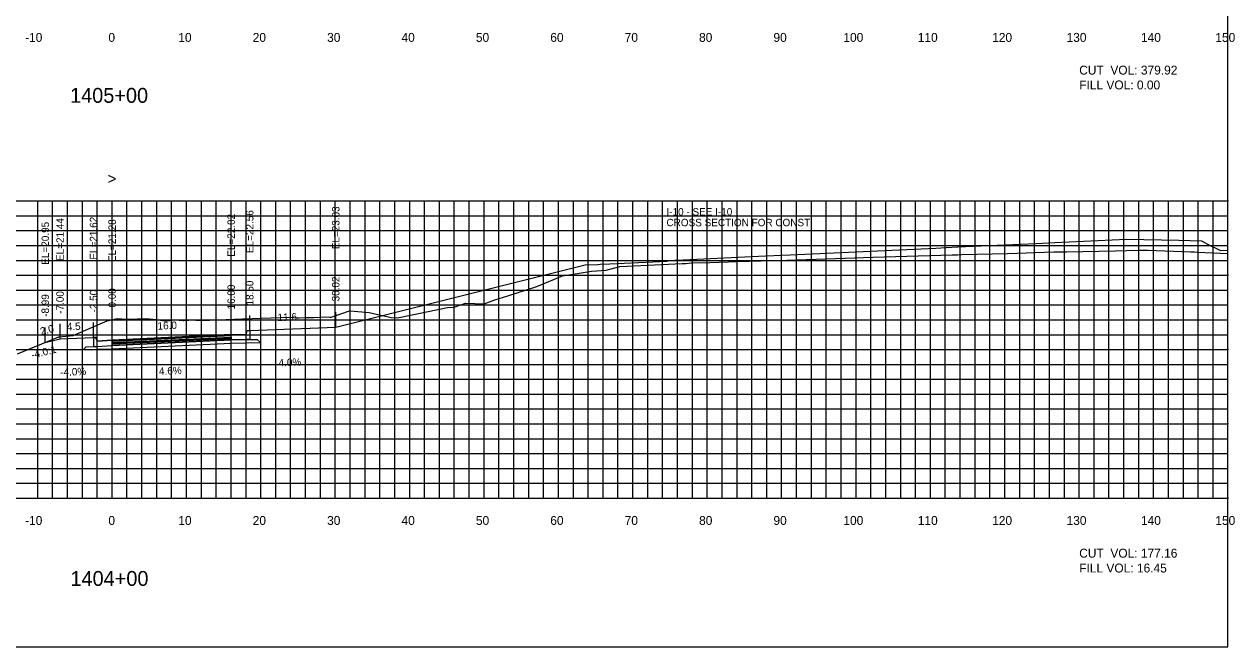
# Model space of a CAD drawing. Extents: x 1797652 to 1804159, y 242516 to 246906.
# Drawn here: x 1803312.7 to 1803475.4, y 242516 to 242599.8 of the extents above; entities that cross this region are included whole.
import ezdxf

# ---------------------------------------------------------------- set-up
doc = ezdxf.new("R2010")
doc.units = 0
for name, color, linetype in [('1', 7, 'Continuous'), ('10', 7, 'Continuous'), ('2', 7, 'Continuous'), ('3', 7, 'Continuous'), ('4', 7, 'Continuous'), ('60', 7, 'Continuous'), ('BASE', 7, 'Continuous'), ('CL-CNST', 7, 'Continuous'), ('Level 62', 7, 'Continuous'), ('LOWER BINDER', 7, 'Continuous'), ('M-ROADS', 7, 'Continuous'), ('UPPER BINDER', 7, 'Continuous')]:
    doc.layers.add(name, color=color, linetype=linetype)

msp = doc.modelspace()

# ---------------------------------------------------------------- linework, layer by layer
for p, q in [((1803342.99, 242558.56), (1803342.99, 242560.56)), ((1803354.55, 242559.03), (1803354.55, 242561.03)), ((1803315.5, 242556.95), (1803315.5, 242558.95)), ((1803317.49, 242557.44), (1803317.49, 242559.44)), ((1803321.99, 242557.62), (1803321.99, 242559.62)), ((1803324.49, 242557.28), (1803324.49, 242559.28)), ((1803340.49, 242558.02), (1803340.49, 242560.02))]:
    msp.add_line(p, q)
for points in [[(1803174.49, 242516), (1803474.49, 242516), (1803474.49, 242706), (1803174.49, 242706)], [(1803340.49, 242558.02), (1803342.49, 242558.06), (1803342.66, 242558.56), (1803342.99, 242558.56), (1803342.99, 242557.34), (1803342.49, 242557.34), (1803340.49, 242557.3)], [(1803324.49, 242557.28), (1803322.49, 242557.12), (1803322.32, 242557.62), (1803321.99, 242557.62), (1803321.98, 242556.4), (1803322.48, 242556.4), (1803324.49, 242556.56)]]:
    msp.add_lwpolyline(points, close=True)
at = {"layer": '2'}
msp.add_lwpolyline([(1803340.49, 242557.87), (1803340.49, 242558.02), (1803324.49, 242557.28), (1803324.49, 242557.13)], close=True, dxfattribs=at)
at = {"layer": '60'}
for p, q in [((1803474.49, 242536), (1803474.49, 242576)), ((1803474.55, 242576), (1803474.49, 242576)), ((1803474.55, 242566), (1803474.49, 242566)), ((1803474.55, 242556), (1803474.49, 242556)), ((1803474.55, 242546), (1803474.49, 242546)), ((1803174.49, 242536), (1803474.49, 242536)), ((1803314.49, 242535.94), (1803314.49, 242536)), ((1803324.49, 242535.94), (1803324.49, 242536)), ((1803334.49, 242535.94), (1803334.49, 242536)), ((1803344.49, 242535.94), (1803344.49, 242536)), ((1803354.49, 242535.94), (1803354.49, 242536)), ((1803364.49, 242535.94), (1803364.49, 242536)), ((1803374.49, 242535.94), (1803374.49, 242536)), ((1803384.49, 242535.94), (1803384.49, 242536)), ((1803394.49, 242535.94), (1803394.49, 242536)), ((1803404.49, 242535.94), (1803404.49, 242536)), ((1803414.49, 242535.94), (1803414.49, 242536)), ((1803424.49, 242535.94), (1803424.49, 242536)), ((1803434.49, 242535.94), (1803434.49, 242536)), ((1803444.49, 242535.94), (1803444.49, 242536)), ((1803454.49, 242535.94), (1803454.49, 242536)), ((1803464.49, 242535.94), (1803464.49, 242536)), ((1803474.49, 242535.94), (1803474.49, 242536)), ((1803474.55, 242536), (1803474.49, 242536))]:
    msp.add_line(p, q, dxfattribs=at)
at = {"layer": 'BASE'}
msp.add_lwpolyline([(1803324.49, 242556.56), (1803340.49, 242557.3), (1803342.49, 242557.34), (1803342.99, 242557.34), (1803343.99, 242557.37), (1803344.47, 242556.89), (1803340.49, 242556.8), (1803324.49, 242556.06), (1803320.58, 242555.98), (1803320.98, 242556.38), (1803321.98, 242556.4), (1803322.48, 242556.4)], close=True, dxfattribs=at)
at = {"layer": 'CL-CNST'}
for points in [[(1803354.55, 242559.03), (1803383.24, 242566.17), (1803388.08, 242567.38), (1803389.79, 242567.46), (1803390.1, 242567.47), (1803391.39, 242567.53), (1803399.12, 242567.9), (1803399.19, 242567.97), (1803399.2, 242567.98), (1803400.12, 242568.01), (1803400.21, 242568.02), (1803401.24, 242568.07), (1803412.34, 242568.59), (1803415.62, 242568.74), (1803424.47, 242569.15), (1803435.2, 242569.66), (1803436.59, 242569.72), (1803438.18, 242569.8), (1803448.71, 242570.29), (1803451.21, 242570.41), (1803460.83, 242570.86), (1803467.87, 242570.7), (1803470.93, 242570.63), (1803471.75, 242570.2), (1803473.46, 242569.32), (1803474.49, 242569.37)], [(1803315.5, 242556.95), (1803317.49, 242557.44), (1803321.99, 242557.62), (1803322.32, 242557.62), (1803322.49, 242557.12), (1803324.49, 242557.28), (1803340.49, 242558.02), (1803342.49, 242558.06), (1803342.66, 242558.56), (1803342.99, 242558.56), (1803354.55, 242559.03)]]:
    msp.add_lwpolyline(points, dxfattribs=at)
at = {"layer": 'Level 62'}
for p, q in [((1803174.49, 242576), (1803474.49, 242576)), ((1803314.49, 242536), (1803314.49, 242576)), ((1803316.49, 242536), (1803316.49, 242576)), ((1803318.49, 242536), (1803318.49, 242576)), ((1803320.49, 242536), (1803320.49, 242576)), ((1803322.49, 242536), (1803322.49, 242576)), ((1803324.49, 242536), (1803324.49, 242576)), ((1803326.49, 242536), (1803326.49, 242576)), ((1803328.49, 242536), (1803328.49, 242576)), ((1803330.49, 242536), (1803330.49, 242576)), ((1803332.49, 242536), (1803332.49, 242576)), ((1803334.49, 242536), (1803334.49, 242576)), ((1803336.49, 242536), (1803336.49, 242576)), ((1803338.49, 242536), (1803338.49, 242576)), ((1803340.49, 242536), (1803340.49, 242576)), ((1803342.49, 242536), (1803342.49, 242576)), ((1803344.49, 242536), (1803344.49, 242576)), ((1803346.49, 242536), (1803346.49, 242576)), ((1803348.49, 242536), (1803348.49, 242576)), ((1803350.49, 242536), (1803350.49, 242576)), ((1803352.49, 242536), (1803352.49, 242576)), ((1803354.49, 242536), (1803354.49, 242576)), ((1803356.49, 242536), (1803356.49, 242576)), ((1803358.49, 242536), (1803358.49, 242576)), ((1803360.49, 242536), (1803360.49, 242576)), ((1803362.49, 242536), (1803362.49, 242576)), ((1803364.49, 242536), (1803364.49, 242576)), ((1803366.49, 242536), (1803366.49, 242576)), ((1803368.49, 242536), (1803368.49, 242576)), ((1803370.49, 242536), (1803370.49, 242576)), ((1803372.49, 242536), (1803372.49, 242576)), ((1803374.49, 242536), (1803374.49, 242576)), ((1803376.49, 242536), (1803376.49, 242576)), ((1803378.49, 242536), (1803378.49, 242576)), ((1803380.49, 242536), (1803380.49, 242576)), ((1803382.49, 242536), (1803382.49, 242576)), ((1803384.49, 242536), (1803384.49, 242576)), ((1803386.49, 242536), (1803386.49, 242576)), ((1803388.49, 242536), (1803388.49, 242576)), ((1803390.49, 242536), (1803390.49, 242576)), ((1803392.49, 242536), (1803392.49, 242576)), ((1803394.49, 242536), (1803394.49, 242576)), ((1803396.49, 242536), (1803396.49, 242576)), ((1803398.49, 242536), (1803398.49, 242576)), ((1803400.49, 242536), (1803400.49, 242576)), ((1803402.49, 242536), (1803402.49, 242576)), ((1803404.49, 242536), (1803404.49, 242576)), ((1803406.49, 242536), (1803406.49, 242576)), ((1803408.49, 242536), (1803408.49, 242576)), ((1803410.49, 242536), (1803410.49, 242576)), ((1803412.49, 242536), (1803412.49, 242576)), ((1803414.49, 242536), (1803414.49, 242576)), ((1803416.49, 242536), (1803416.49, 242576)), ((1803418.49, 242536), (1803418.49, 242576)), ((1803420.49, 242536), (1803420.49, 242576)), ((1803422.49, 242536), (1803422.49, 242576)), ((1803424.49, 242536), (1803424.49, 242576)), ((1803426.49, 242536), (1803426.49, 242576)), ((1803428.49, 242536), (1803428.49, 242576)), ((1803430.49, 242536), (1803430.49, 242576)), ((1803432.49, 242536), (1803432.49, 242576)), ((1803434.49, 242536), (1803434.49, 242576)), ((1803436.49, 242536), (1803436.49, 242576)), ((1803438.49, 242536), (1803438.49, 242576)), ((1803440.49, 242536), (1803440.49, 242576)), ((1803442.49, 242536), (1803442.49, 242576)), ((1803444.49, 242536), (1803444.49, 242576)), ((1803446.49, 242536), (1803446.49, 242576)), ((1803448.49, 242536), (1803448.49, 242576)), ((1803450.49, 242536), (1803450.49, 242576)), ((1803452.49, 242536), (1803452.49, 242576)), ((1803454.49, 242536), (1803454.49, 242576)), ((1803456.49, 242536), (1803456.49, 242576)), ((1803458.49, 242536), (1803458.49, 242576)), ((1803460.49, 242536), (1803460.49, 242576)), ((1803462.49, 242536), (1803462.49, 242576)), ((1803464.49, 242536), (1803464.49, 242576)), ((1803466.49, 242536), (1803466.49, 242576)), ((1803468.49, 242536), (1803468.49, 242576)), ((1803470.49, 242536), (1803470.49, 242576)), ((1803472.49, 242536), (1803472.49, 242576)), ((1803474.49, 242536), (1803474.49, 242576)), ((1803174.49, 242574), (1803474.49, 242574)), ((1803174.49, 242572), (1803474.49, 242572)), ((1803174.49, 242570), (1803474.49, 242570)), ((1803174.49, 242568), (1803474.49, 242568)), ((1803174.49, 242566), (1803474.49, 242566)), ((1803174.49, 242564), (1803474.49, 242564)), ((1803174.49, 242562), (1803474.49, 242562)), ((1803174.49, 242560), (1803474.49, 242560)), ((1803174.49, 242558), (1803474.49, 242558)), ((1803174.49, 242556), (1803474.49, 242556)), ((1803174.49, 242554), (1803474.49, 242554)), ((1803174.49, 242552), (1803474.49, 242552)), ((1803174.49, 242550), (1803474.49, 242550)), ((1803174.49, 242548), (1803474.49, 242548)), ((1803174.49, 242546), (1803474.49, 242546)), ((1803174.49, 242544), (1803474.49, 242544)), ((1803174.49, 242542), (1803474.49, 242542)), ((1803174.49, 242540), (1803474.49, 242540)), ((1803174.49, 242538), (1803474.49, 242538)), ((1803174.49, 242536), (1803474.49, 242536))]:
    msp.add_line(p, q, dxfattribs=at)
at = {"layer": 'LOWER BINDER'}
for points in [[(1803324.49, 242556.75), (1803324.49, 242556.94), (1803340.49, 242557.68), (1803340.49, 242557.49)], [(1803324.49, 242556.56), (1803324.49, 242556.75), (1803340.49, 242557.49), (1803340.49, 242557.3)]]:
    msp.add_lwpolyline(points, close=True, dxfattribs=at)
at = {"layer": 'M-ROADS'}
msp.add_lwpolyline([(1803311.78, 242555.42), (1803317.34, 242557.7), (1803319.26, 242557.91), (1803323.83, 242559.87), (1803325.17, 242560.18), (1803326.45, 242560.1), (1803326.69, 242560.1), (1803329.06, 242560.18), (1803330.39, 242560.06), (1803330.7, 242560.02), (1803331.2, 242559.9), (1803331.51, 242559.86), (1803331.9, 242559.88), (1803332.94, 242559.99), (1803332.97, 242559.99), (1803334.04, 242559.92), (1803334.15, 242559.92), (1803334.2, 242559.94), (1803334.29, 242559.93), (1803335.26, 242560), (1803335.76, 242559.97), (1803336.47, 242559.89), (1803342.02, 242560.11), (1803348.44, 242560.36), (1803349.32, 242560.26), (1803349.63, 242560.26), (1803350.54, 242560.31), (1803350.72, 242560.31), (1803351.21, 242560.31), (1803351.6, 242560.31), (1803351.94, 242560.34), (1803352.08, 242560.33), (1803353, 242560.38), (1803353.74, 242560.37), (1803353.95, 242560.37), (1803356.38, 242561.19), (1803356.47, 242561.19), (1803356.55, 242561.23), (1803359.06, 242560.99), (1803361.98, 242560.33), (1803362.83, 242560.26), (1803369.57, 242561.67), (1803370.45, 242561.72), (1803371.98, 242562.22), (1803374.52, 242562.16), (1803375.95, 242562.68), (1803377.68, 242563.24), (1803381.59, 242564.5), (1803385.04, 242565.94), (1803387.52, 242566.32), (1803388.95, 242566.55), (1803390.92, 242566.69), (1803392.74, 242567.18), (1803392.78, 242567.18), (1803401.1, 242567.56), (1803401.61, 242567.59), (1803402.36, 242567.66), (1803404.83, 242567.72), (1803408.54, 242567.84), (1803411.75, 242567.92), (1803413.89, 242567.98), (1803423.02, 242568.28), (1803426.76, 242568.41), (1803437.43, 242568.74), (1803438.11, 242568.76), (1803438.65, 242568.77), (1803444.83, 242568.94), (1803451.1, 242569.14), (1803451.64, 242569.15), (1803452.8, 242569.17), (1803459.37, 242569.29), (1803462.41, 242569.35), (1803463.12, 242569.35), (1803463.68, 242569.35), (1803469.5, 242569.15), (1803469.99, 242569.14), (1803470.36, 242569.12), (1803474.49, 242568.94)], dxfattribs=at)
at = {"layer": 'UPPER BINDER'}
msp.add_lwpolyline([(1803340.49, 242557.68), (1803340.49, 242557.87), (1803324.49, 242557.13), (1803324.49, 242556.94)], close=True, dxfattribs=at)

# ---------------------------------------------------------------- texts
msp.add_text('-4.0:1', height=1, rotation=14.0362).set_placement((1803313.75, 242554.77))
at = {"layer": '1'}
for s, p in [('1405+00', (1803318.84, 242589.2)), ('1404+00', (1803318.89, 242524.2))]:
    msp.add_text(s, height=2, dxfattribs=at).set_placement(p)
at = {"layer": '10'}
for s, p in [('-10', (1803312.79, 242597.4)), ('0', (1803323.99, 242597.4)), ('10', (1803333.39, 242597.4)), ('20', (1803343.39, 242597.4)), ('30', (1803353.39, 242597.4)), ('40', (1803363.39, 242597.4)), ('50', (1803373.39, 242597.4)), ('60', (1803383.39, 242597.4)), ('70', (1803393.39, 242597.4)), ('80', (1803403.39, 242597.4)), ('90', (1803413.39, 242597.4)), ('100', (1803422.79, 242597.4)), ('110', (1803432.79, 242597.4)), ('120', (1803442.79, 242597.4)), ('130', (1803452.79, 242597.4)), ('140', (1803462.79, 242597.4)), ('150', (1803472.79, 242597.4)), ('CUT  VOL: 379.92', (1803454.49, 242593)), ('FILL VOL: 0.00', (1803454.49, 242591)), ('-10', (1803312.79, 242532.4)), ('0', (1803323.99, 242532.4)), ('10', (1803333.39, 242532.4)), ('20', (1803343.39, 242532.4)), ('30', (1803353.39, 242532.4)), ('40', (1803363.39, 242532.4)), ('50', (1803373.39, 242532.4)), ('60', (1803383.39, 242532.4)), ('70', (1803393.39, 242532.4)), ('80', (1803403.39, 242532.4)), ('90', (1803413.39, 242532.4)), ('100', (1803422.79, 242532.4)), ('110', (1803432.79, 242532.4)), ('120', (1803442.79, 242532.4)), ('130', (1803452.79, 242532.4)), ('140', (1803462.79, 242532.4)), ('150', (1803472.79, 242532.4)), ('CUT  VOL: 177.16', (1803454.49, 242528)), ('FILL VOL: 16.45', (1803454.49, 242526))]:
    msp.add_text(s, height=1.2, dxfattribs=at).set_placement(p)
at = {"layer": '3'}
for s, p in [('EL=23.03', (1803355.05, 242569.5)), ('EL=21.44', (1803317.99, 242567.92)), ('EL=21.62', (1803322.49, 242568.1)), ('EL=21.28', (1803324.99, 242567.76)), ('EL=22.02', (1803340.99, 242568.49)), ('EL=22.56', (1803343.49, 242568.99)), ('EL=20.95', (1803316, 242567.42)), ('18.50', (1803343.49, 242561.93)), ('30.02', (1803355.05, 242562.48)), ('-7.00', (1803317.99, 242560.81)), ('-2.50', (1803322.49, 242560.99)), ('0.00', (1803324.99, 242561.65)), ('16.00', (1803340.99, 242561.39)), ('-8.99', (1803316, 242560.4))]:
    msp.add_text(s, height=1, rotation=90, dxfattribs=at).set_placement(p)
for s, p in [('I-10 - SEE I-10', (1803399.01, 242574.03)), ('CROSS SECTION FOR CONST ', (1803399.01, 242572.59))]:
    msp.add_text(s, height=1, dxfattribs=at).set_placement(p)
at = {"layer": '4'}
for s, rotation, p in [('11.6', 2.2906, (1803346.75, 242559.82)), ('2.0', 14.0362, (1803314.95, 242557.94)), ('4.5', 2.2906, (1803318.42, 242558.58)), ('16.0', 2.6337, (1803330.62, 242558.67)), ('4.6%', 2.6337, (1803330.81, 242552.57)), ('4.0%', 2.2906, (1803346.89, 242553.72)), ('-4.0%', 2.2906, (1803317.53, 242552.44))]:
    msp.add_text(s, height=1, rotation=rotation, dxfattribs=at).set_placement(p)
at = {"layer": '60'}
msp.add_text('>', height=1.5, dxfattribs=at).set_placement((1803323.88, 242578.25))

doc.saveas('drawing.dxf')
